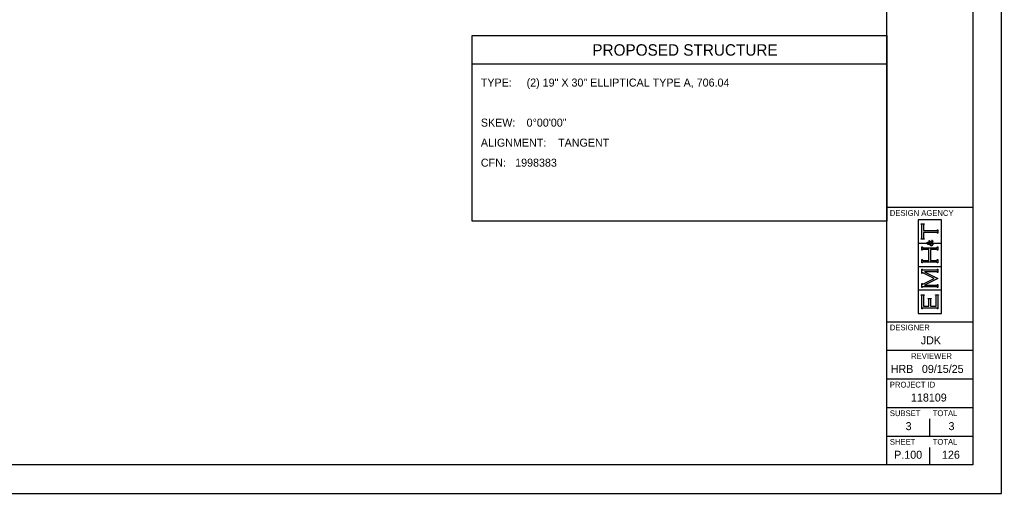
# Model space of a CAD drawing. Extents: x -0.3 to 34, y 0 to 22.
# Drawn here: x 16.84 to 34, y 0 to 8.28 of the extents above; entities that cross this region are included whole.
import ezdxf

# ---------------------------------------------------------------- set-up
doc = ezdxf.new("R2010")
doc.units = 0
for name, color, linetype in [('DT_X_Break_Line', 7, 'Continuous'), ('DT_X_Island', 7, 'Continuous'), ('DT_X_Void', 7, 'Continuous')]:
    doc.layers.add(name, color=color, linetype=linetype)

msp = doc.modelspace()

# ---------------------------------------------------------------- linework, layer by layer
at = {"layer": 'DT_X_Break_Line'}
msp.add_lwpolyline([(0, 0), (34, 0), (34, 22), (0, 22)], close=True, dxfattribs=at)
at = {"layer": 'DT_X_Island'}
for p, q in [((32, 0.5), (32, 21.5)), ((32, 5), (33.5, 5)), ((32, 3), (33.5, 3)), ((32, 2.5), (33.5, 2.5)), ((32, 2), (33.5, 2)), ((32, 1.5), (33.5, 1.5)), ((32, 1), (33.5, 1))]:
    msp.add_line(p, q, dxfattribs=at)
msp.add_lwpolyline([(1.5, 21.5), (33.5, 21.5), (33.5, 0.5), (1.5, 0.5)], close=True, dxfattribs=at)
at = {"layer": 'DT_X_Void'}
for p, q in [((32, 7.5), (24.75, 7.5)), ((32.952, 4.779), (32.547, 4.779)), ((32.547, 4.779), (32.547, 4.375)), ((32.598, 4.704), (32.598, 4.711)), ((32.598, 4.711), (32.65, 4.711)), ((32.603, 4.703), (32.598, 4.704)), ((32.606, 4.701), (32.603, 4.703)), ((32.608, 4.699), (32.606, 4.701)), ((32.61, 4.696), (32.608, 4.699)), ((32.611, 4.692), (32.61, 4.696)), ((32.611, 4.687), (32.611, 4.692)), ((32.611, 4.468), (32.611, 4.687)), ((32.638, 4.696), (32.637, 4.692)), ((32.637, 4.692), (32.637, 4.687)), ((32.637, 4.687), (32.637, 4.593)), ((32.64, 4.699), (32.638, 4.696)), ((32.642, 4.701), (32.64, 4.699)), ((32.645, 4.703), (32.642, 4.701)), ((32.65, 4.704), (32.645, 4.703)), ((32.65, 4.711), (32.65, 4.704)), ((32.952, 4.375), (32.952, 4.779)), ((32.611, 4.462), (32.611, 4.468)), ((32.637, 4.593), (32.864, 4.593)), ((32.864, 4.561), (32.637, 4.561)), ((32.637, 4.561), (32.637, 4.468)), ((32.637, 4.468), (32.637, 4.462)), ((32.864, 4.593), (32.869, 4.593)), ((32.87, 4.561), (32.864, 4.561)), ((32.869, 4.593), (32.873, 4.594)), ((32.874, 4.56), (32.87, 4.561)), ((32.873, 4.594), (32.876, 4.596)), ((32.876, 4.559), (32.874, 4.56)), ((32.876, 4.596), (32.878, 4.597)), ((32.878, 4.557), (32.876, 4.559)), ((32.878, 4.597), (32.88, 4.601)), ((32.88, 4.553), (32.878, 4.557)), ((32.88, 4.601), (32.881, 4.606)), ((32.881, 4.548), (32.88, 4.553)), ((32.881, 4.606), (32.888, 4.606)), ((32.888, 4.548), (32.881, 4.548)), ((32.888, 4.606), (32.888, 4.548)), ((32.547, 4.375), (32.696, 4.375)), ((32.696, 4.369), (32.547, 4.369)), ((32.547, 4.369), (32.547, 3.965)), ((32.598, 4.45), (32.603, 4.451)), ((32.598, 4.444), (32.598, 4.45)), ((32.65, 4.444), (32.598, 4.444)), ((32.603, 4.451), (32.606, 4.453)), ((32.606, 4.453), (32.608, 4.455)), ((32.608, 4.455), (32.61, 4.458)), ((32.61, 4.458), (32.611, 4.462)), ((32.611, 4.249), (32.611, 4.307)), ((32.611, 4.307), (32.617, 4.307)), ((32.617, 4.307), (32.619, 4.302)), ((32.619, 4.302), (32.62, 4.298)), ((32.62, 4.298), (32.623, 4.297)), ((32.623, 4.297), (32.625, 4.295)), ((32.625, 4.295), (32.629, 4.294)), ((32.629, 4.294), (32.635, 4.294)), ((32.635, 4.294), (32.864, 4.294)), ((32.637, 4.462), (32.638, 4.458)), ((32.638, 4.458), (32.64, 4.455)), ((32.64, 4.455), (32.642, 4.453)), ((32.642, 4.453), (32.645, 4.451)), ((32.645, 4.451), (32.65, 4.45)), ((32.65, 4.45), (32.65, 4.444)), ((32.696, 4.375), (32.696, 4.369)), ((32.703, 4.379), (32.705, 4.383)), ((32.703, 4.373), (32.703, 4.379)), ((32.703, 4.368), (32.703, 4.373)), ((32.705, 4.363), (32.703, 4.368)), ((32.705, 4.383), (32.708, 4.387)), ((32.708, 4.358), (32.705, 4.363)), ((32.708, 4.387), (32.711, 4.39)), ((32.709, 4.379), (32.708, 4.376)), ((32.708, 4.376), (32.708, 4.373)), ((32.708, 4.373), (32.708, 4.369)), ((32.708, 4.369), (32.71, 4.366)), ((32.712, 4.353), (32.708, 4.358)), ((32.712, 4.381), (32.709, 4.379)), ((32.71, 4.366), (32.712, 4.364)), ((32.711, 4.39), (32.715, 4.392)), ((32.714, 4.383), (32.712, 4.381)), ((32.712, 4.364), (32.715, 4.362)), ((32.718, 4.35), (32.712, 4.353)), ((32.716, 4.384), (32.714, 4.383)), ((32.715, 4.392), (32.72, 4.392)), ((32.715, 4.362), (32.718, 4.361)), ((32.72, 4.384), (32.716, 4.384)), ((32.718, 4.361), (32.721, 4.361)), ((32.726, 4.35), (32.718, 4.35)), ((32.72, 4.392), (32.725, 4.392)), ((32.724, 4.384), (32.72, 4.384)), ((32.721, 4.361), (32.723, 4.361)), ((32.723, 4.361), (32.725, 4.362)), ((32.728, 4.382), (32.724, 4.384)), ((32.725, 4.392), (32.729, 4.39)), ((32.725, 4.362), (32.728, 4.362)), ((32.729, 4.35), (32.726, 4.35)), ((32.731, 4.38), (32.728, 4.382)), ((32.728, 4.362), (32.731, 4.363)), ((32.729, 4.39), (32.732, 4.387)), ((32.731, 4.35), (32.729, 4.35)), ((32.734, 4.377), (32.731, 4.38)), ((32.731, 4.363), (32.735, 4.365)), ((32.734, 4.351), (32.731, 4.35)), ((32.732, 4.387), (32.736, 4.383)), ((32.737, 4.372), (32.734, 4.377)), ((32.737, 4.352), (32.734, 4.351)), ((32.735, 4.365), (32.74, 4.367)), ((32.736, 4.383), (32.74, 4.378)), ((32.74, 4.367), (32.737, 4.372)), ((32.741, 4.353), (32.737, 4.352)), ((32.738, 4.393), (32.738, 4.422)), ((32.738, 4.422), (32.741, 4.422)), ((32.741, 4.393), (32.738, 4.393)), ((32.74, 4.378), (32.744, 4.369)), ((32.741, 4.422), (32.741, 4.418)), ((32.741, 4.418), (32.742, 4.415)), ((32.742, 4.396), (32.741, 4.395)), ((32.741, 4.395), (32.741, 4.393)), ((32.746, 4.355), (32.741, 4.353)), ((32.742, 4.415), (32.743, 4.413)), ((32.743, 4.397), (32.742, 4.396)), ((32.743, 4.413), (32.745, 4.411)), ((32.745, 4.399), (32.743, 4.397)), ((32.744, 4.369), (32.754, 4.375)), ((32.745, 4.411), (32.749, 4.408)), ((32.746, 4.399), (32.745, 4.399)), ((32.748, 4.399), (32.746, 4.399)), ((32.752, 4.344), (32.746, 4.355)), ((32.755, 4.399), (32.748, 4.399)), ((32.749, 4.408), (32.756, 4.404)), ((32.756, 4.36), (32.751, 4.357)), ((32.751, 4.357), (32.754, 4.352)), ((32.757, 4.337), (32.752, 4.344)), ((32.754, 4.375), (32.764, 4.381)), ((32.754, 4.352), (32.757, 4.348)), ((32.763, 4.395), (32.755, 4.399)), ((32.756, 4.404), (32.763, 4.4)), ((32.761, 4.363), (32.756, 4.36)), ((32.757, 4.348), (32.761, 4.345)), ((32.763, 4.333), (32.757, 4.337)), ((32.764, 4.365), (32.761, 4.363)), ((32.761, 4.345), (32.765, 4.343)), ((32.763, 4.4), (32.77, 4.396)), ((32.772, 4.387), (32.763, 4.395)), ((32.768, 4.329), (32.763, 4.333)), ((32.764, 4.381), (32.772, 4.387)), ((32.768, 4.367), (32.764, 4.365)), ((32.765, 4.343), (32.769, 4.341)), ((32.774, 4.372), (32.768, 4.367)), ((32.774, 4.327), (32.768, 4.329)), ((32.769, 4.341), (32.773, 4.341)), ((32.77, 4.396), (32.776, 4.391)), ((32.773, 4.341), (32.778, 4.341)), ((32.782, 4.378), (32.774, 4.372)), ((32.779, 4.327), (32.774, 4.327)), ((32.776, 4.391), (32.781, 4.395)), ((32.778, 4.341), (32.782, 4.343)), ((32.779, 4.423), (32.781, 4.426)), ((32.782, 4.422), (32.779, 4.423)), ((32.785, 4.327), (32.779, 4.327)), ((32.781, 4.426), (32.787, 4.424)), ((32.781, 4.395), (32.784, 4.398)), ((32.785, 4.421), (32.782, 4.422)), ((32.786, 4.373), (32.782, 4.378)), ((32.782, 4.343), (32.786, 4.346)), ((32.784, 4.398), (32.786, 4.401)), ((32.786, 4.419), (32.785, 4.421)), ((32.79, 4.329), (32.785, 4.327)), ((32.788, 4.417), (32.786, 4.419)), ((32.786, 4.401), (32.788, 4.404)), ((32.791, 4.386), (32.786, 4.381)), ((32.786, 4.381), (32.791, 4.376)), ((32.788, 4.369), (32.786, 4.373)), ((32.786, 4.346), (32.789, 4.349)), ((32.787, 4.424), (32.792, 4.421)), ((32.789, 4.414), (32.788, 4.417)), ((32.788, 4.404), (32.789, 4.408)), ((32.79, 4.367), (32.788, 4.369)), ((32.789, 4.411), (32.789, 4.414)), ((32.789, 4.408), (32.789, 4.411)), ((32.789, 4.349), (32.791, 4.353)), ((32.791, 4.364), (32.79, 4.367)), ((32.793, 4.334), (32.79, 4.329)), ((32.794, 4.39), (32.791, 4.386)), ((32.791, 4.376), (32.795, 4.37)), ((32.791, 4.361), (32.791, 4.364)), ((32.791, 4.359), (32.791, 4.361)), ((32.791, 4.353), (32.791, 4.359)), ((32.792, 4.421), (32.795, 4.418)), ((32.797, 4.338), (32.793, 4.334)), ((32.796, 4.394), (32.794, 4.39)), ((32.795, 4.418), (32.798, 4.414)), ((32.795, 4.37), (32.797, 4.366)), ((32.798, 4.397), (32.796, 4.394)), ((32.797, 4.366), (32.798, 4.361)), ((32.799, 4.344), (32.797, 4.338)), ((32.798, 4.414), (32.799, 4.41)), ((32.799, 4.401), (32.798, 4.397)), ((32.798, 4.361), (32.799, 4.357)), ((32.799, 4.41), (32.799, 4.405)), ((32.799, 4.405), (32.799, 4.401)), ((32.803, 4.369), (32.799, 4.375)), ((32.799, 4.375), (32.952, 4.375)), ((32.799, 4.357), (32.799, 4.352)), ((32.799, 4.352), (32.799, 4.344)), ((32.952, 4.369), (32.803, 4.369)), ((32.864, 4.294), (32.869, 4.294)), ((32.869, 4.294), (32.873, 4.295)), ((32.873, 4.295), (32.876, 4.297)), ((32.876, 4.297), (32.878, 4.298)), ((32.878, 4.298), (32.88, 4.302)), ((32.88, 4.302), (32.881, 4.307)), ((32.881, 4.307), (32.888, 4.307)), ((32.888, 4.307), (32.888, 4.249)), ((32.952, 3.965), (32.952, 4.369)), ((32.617, 4.249), (32.611, 4.249)), ((32.618, 4.254), (32.617, 4.249)), ((32.62, 4.258), (32.618, 4.254)), ((32.623, 4.26), (32.62, 4.258)), ((32.625, 4.261), (32.623, 4.26)), ((32.629, 4.262), (32.625, 4.261)), ((32.635, 4.262), (32.629, 4.262)), ((32.732, 4.262), (32.635, 4.262)), ((32.732, 4.072), (32.732, 4.262)), ((32.864, 4.262), (32.759, 4.262)), ((32.759, 4.262), (32.759, 4.072)), ((32.87, 4.262), (32.864, 4.262)), ((32.874, 4.261), (32.87, 4.262)), ((32.876, 4.26), (32.874, 4.261)), ((32.878, 4.258), (32.876, 4.26)), ((32.88, 4.254), (32.878, 4.258)), ((32.881, 4.249), (32.88, 4.254)), ((32.888, 4.249), (32.881, 4.249)), ((32.547, 3.965), (32.952, 3.965)), ((32.952, 3.959), (32.547, 3.959)), ((32.547, 3.959), (32.547, 3.555)), ((32.611, 4.027), (32.611, 4.085)), ((32.611, 4.085), (32.617, 4.085)), ((32.617, 4.027), (32.611, 4.027)), ((32.617, 4.085), (32.619, 4.08)), ((32.618, 4.032), (32.617, 4.027)), ((32.62, 4.036), (32.618, 4.032)), ((32.619, 4.08), (32.62, 4.076)), ((32.62, 4.076), (32.623, 4.074)), ((32.623, 4.037), (32.62, 4.036)), ((32.623, 4.074), (32.625, 4.073)), ((32.625, 4.039), (32.623, 4.037)), ((32.625, 4.073), (32.629, 4.072)), ((32.629, 4.04), (32.625, 4.039)), ((32.629, 4.072), (32.635, 4.072)), ((32.635, 4.04), (32.629, 4.04)), ((32.635, 4.072), (32.732, 4.072)), ((32.864, 4.04), (32.635, 4.04)), ((32.75, 4), (32.75, 4)), ((32.759, 4.072), (32.864, 4.072)), ((32.864, 4.072), (32.87, 4.072)), ((32.87, 4.04), (32.864, 4.04)), ((32.87, 4.072), (32.874, 4.073)), ((32.874, 4.039), (32.87, 4.04)), ((32.874, 4.073), (32.876, 4.074)), ((32.876, 4.038), (32.874, 4.039)), ((32.876, 4.074), (32.878, 4.076)), ((32.878, 4.036), (32.876, 4.038)), ((32.878, 4.076), (32.88, 4.08)), ((32.88, 4.032), (32.878, 4.036)), ((32.88, 4.08), (32.881, 4.085)), ((32.881, 4.027), (32.88, 4.032)), ((32.881, 4.085), (32.888, 4.085)), ((32.888, 4.027), (32.881, 4.027)), ((32.888, 4.085), (32.888, 4.027)), ((32.952, 3.555), (32.952, 3.959)), ((32.611, 3.845), (32.611, 3.918)), ((32.611, 3.918), (32.617, 3.918)), ((32.617, 3.845), (32.611, 3.845)), ((32.617, 3.918), (32.619, 3.912)), ((32.62, 3.852), (32.617, 3.845)), ((32.619, 3.912), (32.62, 3.909)), ((32.62, 3.909), (32.623, 3.907)), ((32.622, 3.855), (32.62, 3.852)), ((32.626, 3.855), (32.622, 3.855)), ((32.623, 3.907), (32.625, 3.905)), ((32.625, 3.905), (32.629, 3.905)), ((32.629, 3.855), (32.626, 3.855)), ((32.629, 3.905), (32.635, 3.905)), ((32.633, 3.853), (32.629, 3.855)), ((32.64, 3.85), (32.633, 3.853)), ((32.635, 3.905), (32.864, 3.905)), ((32.825, 3.757), (32.64, 3.85)), ((32.864, 3.873), (32.654, 3.873)), ((32.654, 3.873), (32.888, 3.755)), ((32.864, 3.905), (32.869, 3.905)), ((32.87, 3.873), (32.864, 3.873)), ((32.869, 3.905), (32.873, 3.905)), ((32.874, 3.872), (32.87, 3.873)), ((32.873, 3.905), (32.876, 3.907)), ((32.876, 3.87), (32.874, 3.872)), ((32.876, 3.907), (32.878, 3.909)), ((32.878, 3.869), (32.876, 3.87)), ((32.878, 3.909), (32.88, 3.912)), ((32.88, 3.865), (32.878, 3.869)), ((32.88, 3.912), (32.881, 3.918)), ((32.881, 3.86), (32.88, 3.865)), ((32.881, 3.918), (32.888, 3.918)), ((32.888, 3.86), (32.881, 3.86)), ((32.888, 3.918), (32.888, 3.86)), ((32.611, 3.596), (32.611, 3.668)), ((32.611, 3.668), (32.617, 3.668)), ((32.617, 3.668), (32.62, 3.662)), ((32.62, 3.605), (32.618, 3.602)), ((32.62, 3.662), (32.622, 3.658)), ((32.623, 3.607), (32.62, 3.605)), ((32.622, 3.658), (32.626, 3.658)), ((32.625, 3.609), (32.623, 3.607)), ((32.629, 3.609), (32.625, 3.609)), ((32.626, 3.658), (32.627, 3.658)), ((32.627, 3.658), (32.633, 3.661)), ((32.635, 3.609), (32.629, 3.609)), ((32.633, 3.661), (32.641, 3.665)), ((32.864, 3.609), (32.635, 3.609)), ((32.641, 3.665), (32.825, 3.757)), ((32.888, 3.755), (32.654, 3.638)), ((32.654, 3.638), (32.864, 3.638)), ((32.864, 3.638), (32.869, 3.638)), ((32.87, 3.609), (32.864, 3.609)), ((32.869, 3.638), (32.873, 3.639)), ((32.874, 3.609), (32.87, 3.609)), ((32.873, 3.639), (32.876, 3.641)), ((32.876, 3.607), (32.874, 3.609)), ((32.876, 3.641), (32.878, 3.643)), ((32.878, 3.605), (32.876, 3.607)), ((32.878, 3.643), (32.88, 3.646)), ((32.88, 3.602), (32.878, 3.605)), ((32.88, 3.646), (32.881, 3.651)), ((32.881, 3.651), (32.888, 3.651)), ((32.888, 3.651), (32.888, 3.596)), ((32.547, 3.555), (32.952, 3.555)), ((32.952, 3.549), (32.547, 3.549)), ((32.547, 3.549), (32.547, 3.145)), ((32.598, 3.462), (32.598, 3.469)), ((32.598, 3.469), (32.65, 3.469)), ((32.603, 3.461), (32.598, 3.462)), ((32.606, 3.459), (32.603, 3.461)), ((32.608, 3.457), (32.606, 3.459)), ((32.61, 3.455), (32.608, 3.457)), ((32.611, 3.451), (32.61, 3.455)), ((32.617, 3.596), (32.611, 3.596)), ((32.611, 3.445), (32.611, 3.451)), ((32.611, 3.225), (32.611, 3.445)), ((32.618, 3.602), (32.617, 3.596)), ((32.64, 3.457), (32.638, 3.455)), ((32.638, 3.455), (32.638, 3.451)), ((32.638, 3.451), (32.638, 3.445)), ((32.638, 3.445), (32.638, 3.27)), ((32.642, 3.459), (32.64, 3.457)), ((32.645, 3.461), (32.642, 3.459)), ((32.65, 3.462), (32.645, 3.461)), ((32.65, 3.469), (32.65, 3.462)), ((32.848, 3.465), (32.848, 3.472)), ((32.848, 3.472), (32.901, 3.472)), ((32.853, 3.464), (32.848, 3.465)), ((32.857, 3.462), (32.853, 3.464)), ((32.859, 3.46), (32.857, 3.462)), ((32.86, 3.458), (32.859, 3.46)), ((32.861, 3.453), (32.86, 3.458)), ((32.861, 3.448), (32.861, 3.453)), ((32.861, 3.27), (32.861, 3.448)), ((32.881, 3.596), (32.88, 3.602)), ((32.888, 3.596), (32.881, 3.596)), ((32.889, 3.457), (32.888, 3.453)), ((32.888, 3.453), (32.888, 3.448)), ((32.888, 3.448), (32.888, 3.225)), ((32.891, 3.46), (32.889, 3.457)), ((32.892, 3.462), (32.891, 3.46)), ((32.896, 3.464), (32.892, 3.462)), ((32.901, 3.465), (32.896, 3.464)), ((32.901, 3.472), (32.901, 3.465)), ((32.952, 3.145), (32.952, 3.549)), ((32.638, 3.27), (32.732, 3.27)), ((32.719, 3.402), (32.719, 3.408)), ((32.719, 3.408), (32.772, 3.408)), ((32.724, 3.401), (32.719, 3.402)), ((32.728, 3.399), (32.724, 3.401)), ((32.729, 3.396), (32.728, 3.399)), ((32.731, 3.394), (32.729, 3.396)), ((32.732, 3.39), (32.731, 3.394)), ((32.732, 3.384), (32.732, 3.39)), ((32.732, 3.27), (32.732, 3.384)), ((32.76, 3.394), (32.759, 3.39)), ((32.759, 3.39), (32.759, 3.384)), ((32.759, 3.384), (32.759, 3.27)), ((32.759, 3.27), (32.861, 3.27)), ((32.761, 3.396), (32.76, 3.394)), ((32.763, 3.399), (32.761, 3.396)), ((32.767, 3.401), (32.763, 3.399)), ((32.772, 3.402), (32.767, 3.401)), ((32.772, 3.408), (32.772, 3.402)), ((32.547, 3.145), (32.952, 3.145)), ((32.617, 3.225), (32.611, 3.225)), ((32.619, 3.23), (32.617, 3.225)), ((32.62, 3.234), (32.619, 3.23)), ((32.623, 3.235), (32.62, 3.234)), ((32.625, 3.237), (32.623, 3.235)), ((32.629, 3.238), (32.625, 3.237)), ((32.635, 3.238), (32.629, 3.238)), ((32.864, 3.238), (32.635, 3.238)), ((32.87, 3.238), (32.864, 3.238)), ((32.874, 3.237), (32.87, 3.238)), ((32.876, 3.235), (32.874, 3.237)), ((32.878, 3.234), (32.876, 3.235)), ((32.88, 3.23), (32.878, 3.234)), ((32.881, 3.225), (32.88, 3.23)), ((32.888, 3.225), (32.881, 3.225)), ((32.75, 1), (32.75, 1.3)), ((32.75, 0.5), (32.75, 0.8)), ((32.375, 0.675), (32.375, 0.675))]:
    msp.add_line(p, q, dxfattribs=at)
msp.add_lwpolyline([(24.75, 8), (32, 8), (32, 4.76), (24.75, 4.76)], close=True, dxfattribs=at)

# ---------------------------------------------------------------- texts
for s, height, p in [('PROPOSED STRUCTURE', 0.2, (26.849, 7.65)), ('TYPE:', 0.14, (24.9, 7.11)), ('(2) 19" X 30" ELLIPTICAL TYPE A, 706.04', 0.14, (25.7, 7.11)), ('SKEW:', 0.14, (24.9, 6.41)), ('0°00\'00"', 0.14, (25.7, 6.41)), ('ALIGNMENT:', 0.14, (24.9, 6.06)), ('TANGENT', 0.14, (26.25, 6.06)), ('CFN:', 0.14, (24.9, 5.71)), ('1998383', 0.14, (25.5, 5.71)), ('DESIGN AGENCY', 0.1, (32.05, 4.85)), ('DESIGNER', 0.1, (32.05, 2.85)), ('JDK', 0.14, (32.592, 2.605)), ('REVIEWER', 0.1, (32.422, 2.35)), ('HRB', 0.14, (32.066, 2.105)), ('09/15/25', 0.14, (32.611, 2.105)), ('PROJECT ID', 0.1, (32.05, 1.85)), ('118109', 0.14, (32.42, 1.605)), ('SUBSET', 0.1, (32.05, 1.35)), ('TOTAL', 0.1, (32.8, 1.35)), ('3', 0.14, (32.326, 1.105)), ('3', 0.14, (33.076, 1.105)), ('SHEET', 0.1, (32.05, 0.85)), ('TOTAL', 0.1, (32.8, 0.85)), ('P.100', 0.14, (32.126, 0.605)), ('126', 0.14, (32.962, 0.605))]:
    msp.add_text(s, height=height, dxfattribs=at).set_placement(p)

doc.saveas('drawing.dxf')
